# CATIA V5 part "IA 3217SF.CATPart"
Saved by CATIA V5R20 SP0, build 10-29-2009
Part number: IA 3217SF
Revision: ANY
Definition: UNKNOWN
Nomenclature: IA 3217SF
Source: Unknown
Bounding box of the stored display mesh (mm): x -1.6 to 1.6, y -8.75 to 8.2, z -1.6 to 1.6
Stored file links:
  C:\Users\Utente\Desktop\IO LAVORO\3D X SITO CF\CUMSA\3D files IA\IA 3217SF\IA 3217SF.CATPart
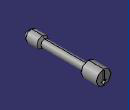
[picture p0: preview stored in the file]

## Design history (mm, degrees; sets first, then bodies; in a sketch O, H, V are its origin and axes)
Body1 "Cortar-Extruir2" (main body)
  Solid1: solid without history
